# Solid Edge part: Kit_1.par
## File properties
Author: ahadarics
Last saved by: ahadarics
Revision: 76
Sűrűség: 0,000 kg/m^3
Pontosság: 0,990
Username: ahadarics
Dokumentum tartalom típus: 0
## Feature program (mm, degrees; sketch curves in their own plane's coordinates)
base feature "unnamed BaseFeature 1"
sketch for "unnamed Hole 1" plane through (-23.25, 23.25, 90) normal (0, 0, 1) x-axis (0, 1, 0)
  hole centre (0, 0) bore radius 3.3235
hole "unnamed Hole 1" through
sketch for "unnamed Hole 2" plane through (-23.25, 23.25, 90) normal (0, 0, 1) x-axis (0, 1, 0)
  hole centre (-46.5, 0) bore radius 3.3235
hole "unnamed Hole 2" through
sketch for "unnamed Hole 3" plane through (-23.25, 23.25, 90) normal (0, 0, 1) x-axis (0, 1, 0)
  hole centre (-46.5, -46.5) bore radius 3.3235
hole "unnamed Hole 3" through
sketch for "unnamed Hole 4" plane through (-23.25, 23.25, 90) normal (0, 0, 1) x-axis (0, 1, 0)
  hole centre (0, -46.5) bore radius 3.3235
hole "unnamed Hole 4" through
pattern "unnamed Pattern 1" of "unnamed Hole 1", "unnamed Hole 2", "unnamed Hole 3", "unnamed Hole 4"
thread "unnamed Thread 1"
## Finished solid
Body 1: solid body, 320 faces, 747 edges, 446 vertices, 4 internal voids.
  Faces by surface: plane 141, cylinder 83, swept 53, torus 22, cone 20, spline 1
  Edges by curve: line 413, circle 177, spline 118, ellipse 28, curve on surface 10, intersection 1
Bounding box of the edges (mm; curved faces can reach further): 65.500 x 65.500 x 14.500, from (-32.75, -32.75, 80.5) to (32.75, 32.75, 95).
Cylindrical faces by radius (mm): R0.2 x40, R0.201 x2, R0.2012 x2, R1.75 x1, R2.5402 x12, R2.6 x4, R3.3235 x4, R3.75 x4, R3.85 x4, R4.283 x1, R5.25 x4, R8.27 x1, R8.85 x1, R9 x1, R10.25 x1, R15.5811 x1
Conical faces (half-angle, radius in mm at the cone's reference point): 0.5 deg R6.5 x2, 0.5 deg R8 x4, 7 deg R9.5925 x1, 14 deg R8.135 x1, 14 deg R8.4811 x1, 17 deg R8.135 x1, 23 deg R8.829 x1, 42.5 deg R8.1233 x1, 45 deg R3.6735 x4, 45 deg R9 x1, 84 deg R8.4608 x1, 85 deg R9.9463 x1, 87 deg R8.1765 x1
Toroidal faces (ring radius, tube radius in mm): R2.9402 r0.4 x12, R3.55 r0.2 x8, R8.8057 r0.2025 x1, R9.2522 r0.2925 x1
Planar faces by outward normal: +x 12, +y 12, +z 24, -x 14, -y 12, -z 1, oblique 66
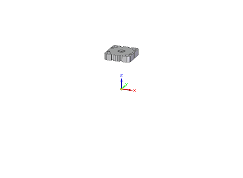
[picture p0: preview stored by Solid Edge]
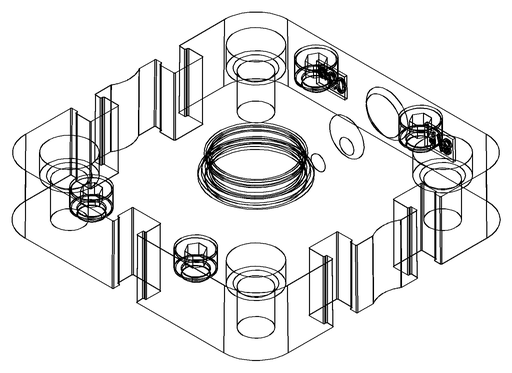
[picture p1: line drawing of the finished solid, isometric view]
